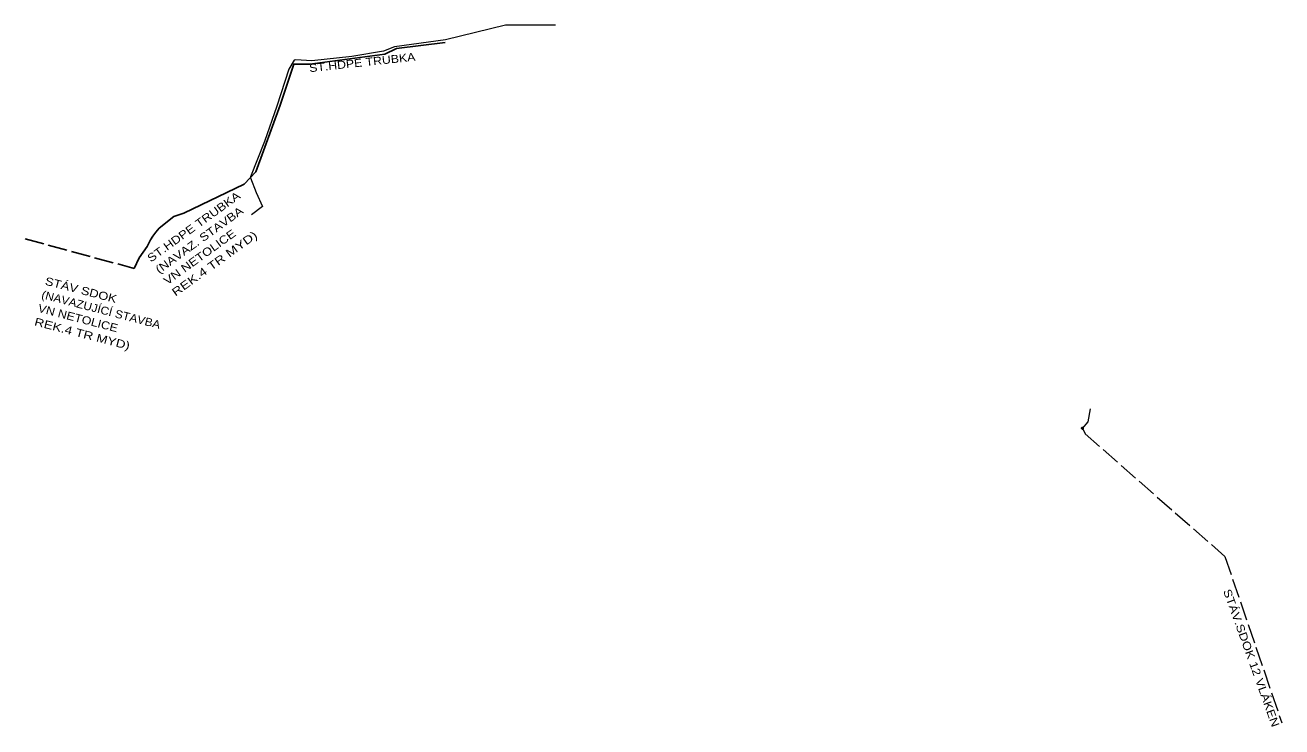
# Model space of a CAD drawing. Extents: x -762644 to -761134, y -1154771 to -1152714.
import ezdxf

# ---------------------------------------------------------------- set-up
doc = ezdxf.new("R2010")
doc.units = 0
doc.header["$LTSCALE"] = 0.8
doc.header["$PDMODE"] = 32
doc.header["$PDSIZE"] = 0.4
doc.linetypes.add('LONG_DASHED', pattern=[7.5, 6, -1.5])
doc.layers.add('2', color=7, linetype='Continuous')
doc.layers.add('42', color=7, linetype='Continuous')
for name, color, linetype, lineweight in [('3', 7, 'LONG_DASHED', 25), ('41', 7, 'Continuous', 25), ('47', 7, 'LONG_DASHED', 25), ('5', 7, 'Continuous', 13)]:
    doc.layers.add(name, color=color, linetype=linetype, lineweight=lineweight)

msp = doc.modelspace()

# ---------------------------------------------------------------- linework, layer by layer
at = {"layer": '3'}
msp.add_line((-762644.228, -1152767.142), (-762616.99, -1152774.51), dxfattribs=at)
at = {"layer": '41'}
msp.add_lwpolyline([(-762616.99, -1152774.51), (-762615.693, -1152771.862), (-762614.703, -1152770.456), (-762613.713, -1152769.049), (-762612.917, -1152767.336), (-762612.301, -1152766.427), (-762611.531, -1152765.459), (-762610.761, -1152764.491), (-762607.026, -1152761.571), (-762604.538, -1152760.671), (-762589.511, -1152753.498), (-762586.581, -1152750.36), (-762580.515, -1152733.738), (-762577.068, -1152723.462), (-762573.036, -1152723.462), (-762554.287, -1152720.944), (-762551.428, -1152719.599), (-762539.227, -1152718.081)], dxfattribs=at)
at = {"layer": '47', "lineweight": 13}
for points in [[(-762379.948, -1152814.501), (-762378.504, -1152812.89), (-762377.881, -1152809.607)], [(-762379.948, -1152814.46), (-762379.272, -1152815.845), (-762344.332, -1152846.483), (-762330.074, -1152888.114)]]:
    msp.add_lwpolyline(points, dxfattribs=at)
at = {"layer": '47'}
msp.add_point((-762379.948, -1152814.46), dxfattribs=at)
at = {"layer": '5'}
msp.add_lwpolyline([(-762511.633, -1152713.722), (-762524.145, -1152713.722), (-762539.171, -1152717.362), (-762551.926, -1152719.11), (-762554.634, -1152720.265), (-762562.571, -1152721.523), (-762572.542, -1152722.617), (-762576.576, -1152722.365), (-762577.007, -1152722.498), (-762578.288, -1152724.735), (-762581.285, -1152733.992), (-762584.418, -1152742.818), (-762587.928, -1152751.659), (-762587.887, -1152751.888), (-762586.494, -1152755.52), (-762584.861, -1152759.012), (-762587.68, -1152761.132)], dxfattribs=at)

# ---------------------------------------------------------------- texts
at = {"layer": '2'}
for s, width, p in [('STÁV SDOK', 1.2, (-762639.417, -1152778.553)), ('(NAVAZUJÍCÍ STAVBA', 1.1, (-762640.298, -1152781.94)), ('VN NETOLICE', 1.15, (-762641.179, -1152785.327)), ('REK.4 TR MYD)', 1.25, (-762642.059, -1152788.715))]:
    msp.add_text(s, height=2, rotation=345.426, dxfattribs=dict(at, width=width)).set_placement(p)
at = {"layer": '42'}
for s, rotation, width, p in [('ST.HDPE TRUBKA', 6.261, 1.15, (-762573.104, -1152725.495)), ('ST.HDPE TRUBKA', 35.822, 1.2, (-762612.788, -1152773.073)), ('(NAVAZ. STAVBA', 35.822, 1.2, (-762610.739, -1152775.91)), ('VN NETOLICE', 35.822, 1.2, (-762608.691, -1152778.748)), ('REK.4 TR MYD)', 35.822, 1.3, (-762606.642, -1152781.586))]:
    msp.add_text(s, height=2, rotation=rotation, dxfattribs=dict(at, width=width)).set_placement(p)
at = {"layer": '47', "width": 1.2}
msp.add_text('STÁV.SDOK 12 VLÁKEN', height=2, rotation=289.738, dxfattribs=at).set_placement((-762344.787, -1152855.079))

doc.saveas('drawing.dxf')
